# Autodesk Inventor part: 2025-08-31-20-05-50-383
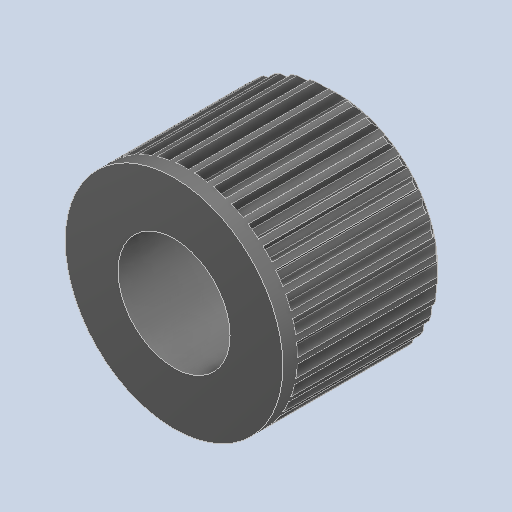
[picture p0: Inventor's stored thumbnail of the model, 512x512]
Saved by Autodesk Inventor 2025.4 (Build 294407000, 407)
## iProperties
Created: 2026-09
Part Number: 2025-08-31-20-05-50-383
Material: Generic
Document SubType Name: Modeling
Designer: AdminForWorker
Density: 1 g/cm^3
Appearance: Default
Title: Gear
Author: AdminForWorker
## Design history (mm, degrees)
feature "Body1"
body "Solid1"
